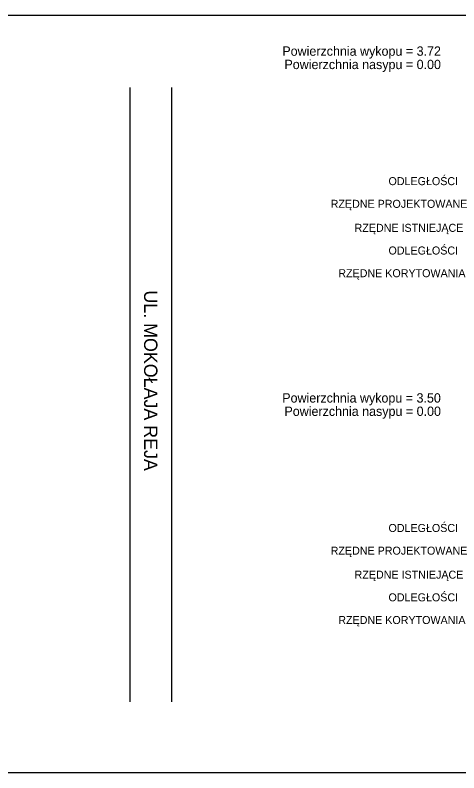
# Model space of a CAD drawing. Extents: x 7492871 to 7493499, y 5802964 to 5802992.
# Drawn here: x 7493159.64 to 7493176.28, y 5802963.88 to 5802992.28 of the extents above; entities that cross this region are included whole.
import ezdxf

# ---------------------------------------------------------------- set-up
doc = ezdxf.new("R2010")
doc.units = 0
for name, color, linetype in [('_wydruk', 7, 'Continuous'), ('d_pop_nasyp_opis', 7, 'Continuous'), ('d_pop_wykop_opis', 7, 'Continuous'), ('opisy_ramki_pop', 7, 'Continuous'), ('pop_opis', 7, 'Continuous'), ('pop_pikietaz', 7, 'Continuous')]:
    doc.layers.add(name, color=color, linetype=linetype)

msp = doc.modelspace()

# ---------------------------------------------------------------- linework, layer by layer
at = {"layer": '_wydruk'}
msp.add_lwpolyline([(7492871.369, 5802992.281), (7493499.283, 5802992.281), (7493499.283, 5802963.881), (7492871.369, 5802963.881)], close=True, dxfattribs=at)
at = {"layer": 'opisy_ramki_pop'}
for p, q in [((7493163.942, 5802989.573), (7493163.942, 5802966.547)), ((7493165.508, 5802989.573), (7493165.508, 5802966.547))]:
    msp.add_line(p, q, dxfattribs=at)

# ---------------------------------------------------------------- texts
at = {"layer": 'd_pop_nasyp_opis'}
for p in [(7493169.738, 5802990.259), (7493169.738, 5802977.259)]:
    msp.add_text('Powierzchnia nasypu = 0.00', height=0.35, dxfattribs=at).set_placement(p)
at = {"layer": 'd_pop_wykop_opis'}
for s, p in [('Powierzchnia wykopu = 3.72', (7493169.659, 5802990.759)), ('Powierzchnia wykopu = 3.50', (7493169.656, 5802977.759))]:
    msp.add_text(s, height=0.35, dxfattribs=at).set_placement(p)
at = {"layer": 'pop_opis'}
for s, p in [('ODLEGŁOŚCI', (7493173.639, 5802985.909)), ('ODLEGŁOŚCI', (7493173.639, 5802985.909)), ('ODLEGŁOŚCI', (7493173.639, 5802985.909)), ('ODLEGŁOŚCI', (7493173.639, 5802985.909)), ('RZĘDNE PROJEKTOWANE', (7493171.471, 5802985.059)), ('RZĘDNE PROJEKTOWANE', (7493171.471, 5802985.059)), ('RZĘDNE PROJEKTOWANE', (7493171.471, 5802985.059)), ('RZĘDNE PROJEKTOWANE', (7493171.471, 5802985.059)), ('RZĘDNE ISTNIEJĄCE', (7493172.367, 5802984.159)), ('ODLEGŁOŚCI', (7493173.639, 5802983.309)), ('RZĘDNE KORYTOWANIA', (7493171.757, 5802982.459)), ('ODLEGŁOŚCI', (7493173.639, 5802972.909)), ('ODLEGŁOŚCI', (7493173.639, 5802972.909)), ('ODLEGŁOŚCI', (7493173.639, 5802972.909)), ('ODLEGŁOŚCI', (7493173.639, 5802972.909)), ('RZĘDNE PROJEKTOWANE', (7493171.471, 5802972.059)), ('RZĘDNE PROJEKTOWANE', (7493171.471, 5802972.059)), ('RZĘDNE PROJEKTOWANE', (7493171.471, 5802972.059)), ('RZĘDNE PROJEKTOWANE', (7493171.471, 5802972.059)), ('RZĘDNE ISTNIEJĄCE', (7493172.367, 5802971.159)), ('ODLEGŁOŚCI', (7493173.639, 5802970.309)), ('RZĘDNE KORYTOWANIA', (7493171.757, 5802969.459))]:
    msp.add_text(s, height=0.3, dxfattribs=at).set_placement(p)
at = {"layer": 'pop_pikietaz'}
msp.add_text('UL. MOKOŁAJA REJA', height=0.5, rotation=270, dxfattribs=at).set_placement((7493164.476, 5802981.963))

doc.saveas('drawing.dxf')
